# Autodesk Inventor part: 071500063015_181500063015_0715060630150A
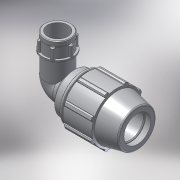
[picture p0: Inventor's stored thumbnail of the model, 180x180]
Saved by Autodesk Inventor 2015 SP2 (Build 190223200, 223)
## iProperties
Created: 2017-02
Part Number: 071500063015_181500063015_0715060630150A
Material: PVC-Piping
Description: PLASSON 90° ELBOW FEMALE ADAPTOR 63-1.1/2"
Document SubType Name: Modeling
Designer: KIM
Mass: 92.6774 g
Surface Area: 199.44 cm^2
Volume: 66.1981 cm^3
Density: 1.4 g/cm^3
Appearance: Smooth - White
Author: KIM
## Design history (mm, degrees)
derived "07150.ipt"
feature "Solid1::07150.ipt"
tag "TaggingFeature1"
body "Solid1"
other parameters: "d2" = 63, "d4" = 13.5, "d5" = 40.5, "d7" = 113, "d9" = 23.14286, "d11" = 5.4, "d13" = 120 deg, "d14" = 81.9, "d15" = 12 deg, "d16" = 98.31, "d18" = 3.15, "d19" = 35 deg, "d20" = 17.5 deg, "d21" = 105.09, "d23" = 0, "d25" = 360 deg, "d27" = 2.26, "d33" = 1.26, "d42" = 59.94, "d43" = 3.39, "d46" = 1.89, "d51" = 162, "d68" = 5.4, "d72" = 69, "d73" = 58.2985, "d74" = 25, "d75" = 67.04327, "d76" = 44.845, "d77" = 27.5, "d79" = 17.938, "d80" = 1.34535, "d83" = 0, "d84" = 0, "d91" = 84.75, "d94" = 44.845, "d95" = 31.3915, "d96" = 13.5, "d97" = 50 deg, "d98" = 40.3605, "d99" = 0.5, "d100" = 0.5, "d101" = 8.33333, "d102" = 58.2985, "d103" = 21.25, "d104" = 0, "d108" = 360 deg, "d110" = 1.74895, "d_" = 63, "E_" = 113, "A_" = 162, "l_2" = 25, "A_1" = 69, "Rp_" = 44.845, "d105" = 8.74477
